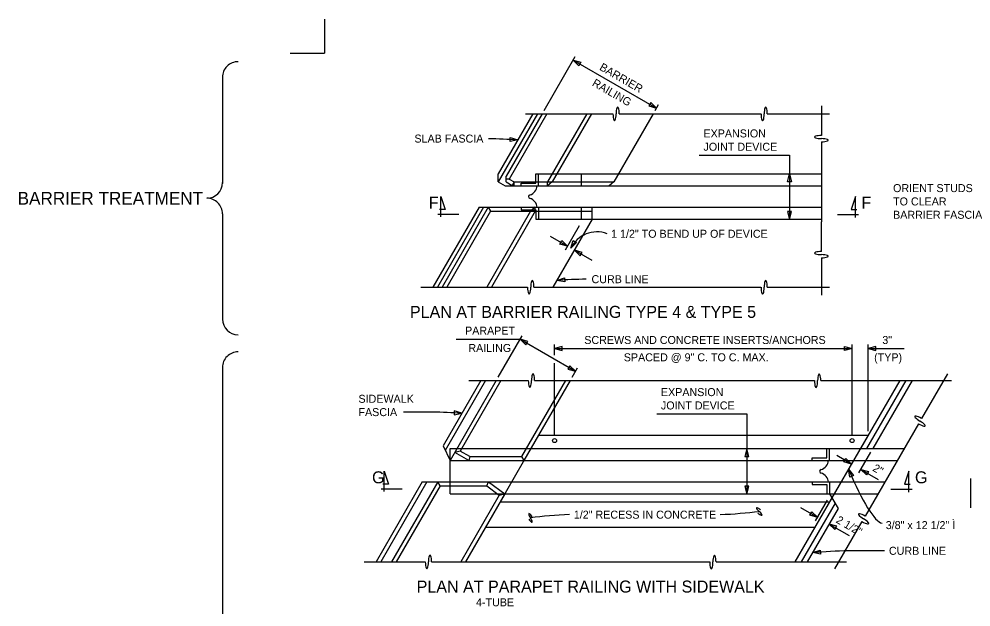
# Model space of a CAD drawing. Extents: x 19590 to 20151, y 19944 to 20103.
# Drawn here: x 19793.8 to 19849.3, y 20063.8 to 20098.1 of the extents above; entities that cross this region are included whole.
import ezdxf

# ---------------------------------------------------------------- set-up
doc = ezdxf.new("R2010")
doc.units = 0
for name, color, linetype in [('DETAIL_PR', 7, 'Continuous'), ('DETAIL_TEXT_DIMEN_PR', 7, 'Continuous'), ('Level 1', 7, 'Continuous'), ('MT_PAVT_MRKGS_EX', 7, 'Continuous'), ('MT_PAVT_MRKGS_EX_REF', 7, 'Continuous'), ('PAVT_MRKGS_QUANT', 7, 'Continuous')]:
    doc.layers.add(name, color=color, linetype=linetype)

# ---------------------------------------------------------------- blocks, each defined once
blk = doc.blocks.new('EJ3H')
at = {"layer": 'MT_PAVT_MRKGS_EX_REF'}
blk.add_text('4-TUBE', height=0.4665, dxfattribs=at).set_placement((8.843, -32.253))

msp = doc.modelspace()

# ---------------------------------------------------------------- linework, layer by layer
at = {"layer": 'DETAIL_PR'}
for p, q in [((19811.624, 20098.097), (19811.624, 20096.106)), ((19809.634, 20096.106), (19811.624, 20096.106)), ((19840.607, 20093.028), (19840.607, 20091.306)), ((19824.053, 20092.561), (19821.763, 20088.596)), ((19823.783, 20092.561), (19821.763, 20089.063)), ((19824.322, 20092.561), (19822.23, 20088.937)), ((19824.591, 20092.561), (19822.4, 20088.767)), ((19823.353, 20092.561), (19828.449, 20092.561)), ((19826.926, 20092.561), (19824.636, 20088.596)), ((19827.195, 20092.561), (19824.905, 20088.596)), ((19830.786, 20092.561), (19828.497, 20088.596)), ((19828.816, 20092.561), (19837.08, 20092.561)), ((19837.447, 20092.561), (19841.074, 20092.561)), ((19840.607, 20090.939), (19840.607, 20086.263)), ((19821.763, 20088.596), (19821.763, 20089.062)), ((19822.23, 20088.596), (19822.23, 20088.937)), ((19822.4, 20088.767), (19822.23, 20088.767)), ((19822.4, 20088.767), (19822.696, 20088.596)), ((19823.948, 20088.518), (19823.948, 20089.063)), ((19823.948, 20089.063), (19828.766, 20089.063)), ((19824.104, 20088.363), (19824.104, 20089.063)), ((19826.611, 20088.363), (19826.611, 20089.063)), ((19828.766, 20089.062), (19840.607, 20089.062)), ((19821.763, 20088.596), (19822.167, 20088.363)), ((19822.167, 20088.363), (19823.093, 20088.363)), ((19822.23, 20088.596), (19822.58, 20088.394)), ((19822.696, 20088.596), (19822.58, 20088.394)), ((19822.58, 20088.394), (19822.696, 20088.363)), ((19822.696, 20088.596), (19828.497, 20088.596)), ((19822.696, 20088.363), (19822.696, 20088.596)), ((19823.093, 20088.363), (19823.093, 20088.518)), ((19823.093, 20088.518), (19823.948, 20088.518)), ((19823.093, 20088.363), (19840.607, 20088.363)), ((19824.636, 20088.363), (19824.636, 20088.596)), ((19824.905, 20088.596), (19824.636, 20088.363)), ((19828.497, 20088.596), (19828.227, 20088.363)), ((19820.641, 20087.119), (19817.947, 20082.454)), ((19820.91, 20087.119), (19818.217, 20082.454)), ((19821.18, 20087.119), (19818.486, 20082.454)), ((19820.641, 20087.119), (19823.968, 20087.119)), ((19821.18, 20087.119), (19821.314, 20086.885)), ((19823.093, 20087.119), (19823.093, 20086.963)), ((19823.093, 20087.119), (19840.607, 20087.119)), ((19823.918, 20087.119), (19823.649, 20086.885)), ((19823.918, 20086.885), (19823.918, 20087.119)), ((19824.104, 20087.119), (19824.104, 20086.419)), ((19826.611, 20086.419), (19826.611, 20087.119)), ((19827.24, 20086.419), (19827.24, 20087.119)), ((19821.314, 20086.886), (19818.755, 20082.454)), ((19823.649, 20086.885), (19821.09, 20082.454)), ((19821.314, 20086.885), (19827.24, 20086.885)), ((19823.918, 20086.885), (19821.359, 20082.454)), ((19823.093, 20086.963), (19823.948, 20086.963)), ((19823.948, 20086.963), (19823.948, 20086.419)), ((19823.948, 20086.419), (19827.24, 20086.419)), ((19827.24, 20086.419), (19824.95, 20082.454)), ((19827.24, 20086.419), (19840.607, 20086.419)), ((19840.607, 20084.542), (19840.607, 20086.263)), ((19840.607, 20084.175), (19840.607, 20081.987)), ((19817.248, 20082.454), (19823.473, 20082.454)), ((19823.84, 20082.454), (19837.08, 20082.454)), ((19837.447, 20082.454), (19841.074, 20082.454))]:
    msp.add_line(p, q, dxfattribs=at)
for centre, radius, start, end in [((19823.421, 20088.428), 0.618, 288.1365, 353.9316), ((19823.621, 20087.741), 0.101, 94.4387, 265.5613), ((19823.421, 20087.053), 0.618, 6.0684, 71.8635)]:
    msp.add_arc(centre, radius, start, end, dxfattribs=at)
for centre, major_axis, ratio, start_param, end_param in [((19828.725, 20092.561), (0, -0.398), 0.230204, 1.570796, 4.712389), ((19837.355, 20092.561), (0, -0.398), 0.230204, 1.570796, 4.712389), ((19828.541, 20092.561), (0, -0.398), 0.230206, 4.712389, 7.853982), ((19837.172, 20092.561), (0, -0.398), 0.230206, 4.712389, 7.853982), ((19840.607, 20091.215), (0.398, 0), 0.230204, 1.570796, 4.712389), ((19840.607, 20091.031), (0.398, 0), 0.230206, 4.712389, 7.853982), ((19840.607, 20084.45), (0.398, 0), 0.230204, 1.570796, 4.712389), ((19840.607, 20084.267), (0.398, 0), 0.230206, 4.712389, 7.853982), ((19823.748, 20082.454), (0, -0.398), 0.230204, 1.570796, 4.712389), ((19837.355, 20082.454), (0, -0.398), 0.230204, 1.570796, 4.712389), ((19823.565, 20082.454), (0, -0.398), 0.230206, 4.712389, 7.853982), ((19837.172, 20082.454), (0, -0.398), 0.230206, 4.712389, 7.853982)]:
    msp.add_ellipse(centre, major_axis=major_axis, ratio=ratio, start_param=start_param, end_param=end_param, dxfattribs=at)
at = {"layer": 'DETAIL_TEXT_DIMEN_PR'}
for p, q in [((19824.439, 20092.764), (19826.252, 20095.904)), ((19826.135, 20095.702), (19830.983, 20092.903)), ((19805.683, 20094.698), (19805.683, 20088.513)), ((19830.903, 20092.764), (19831.1, 20093.105)), ((19833.484, 20090.151), (19838.741, 20090.151)), ((19838.741, 20090.151), (19838.741, 20086.419)), ((19818.412, 20086.56), (19818.411, 20087.741)), ((19818.411, 20087.741), (19818.666, 20086.998)), ((19842.59, 20087.741), (19842.334, 20086.998)), ((19842.589, 20086.532), (19842.59, 20087.741)), ((19805.683, 20086.737), (19805.683, 20080.595)), ((19819.461, 20086.691), (19818.244, 20086.691)), ((19818.666, 20086.998), (19818.333, 20086.998)), ((19841.54, 20086.691), (19842.766, 20086.691)), ((19842.334, 20086.998), (19842.668, 20086.998)), ((19825.678, 20084.647), (19826.495, 20086.061)), ((19824.785, 20085.433), (19825.795, 20084.85)), ((19826.199, 20084.617), (19827.209, 20084.033)), ((19805.683, 20077.779), (19805.683, 20063.131))]:
    msp.add_line(p, q, dxfattribs=at)
for centre, radius, start, end in [((19806.593, 20094.699), 0.91, 89.9663, 180.0337), ((19820.46, 20051.63), 39.492, 86.4465, 88.9222), ((19804.773, 20088.558), 0.911, 269.9663, 359.9663), ((19804.773, 20086.737), 0.91, 359.9663, 90.0337), ((19827.511, 20084.007), 1.679, 69.1378, 154.3845), ((19827.631, 20043.442), 39.492, 91.0778, 93.5535), ((19806.593, 20080.596), 0.91, 180.0337, 270.0337), ((19806.593, 20077.78), 0.91, 89.9663, 180.0337)]:
    msp.add_arc(centre, radius, start, end, dxfattribs=at)
at = {"layer": 'Level 1'}
for p, q in [((19826.135, 20095.702), (19826.584, 20095.577)), ((19826.468, 20095.375), (19826.135, 20095.702)), ((19826.584, 20095.577), (19826.468, 20095.375)), ((19830.65, 20093.23), (19830.534, 20093.028)), ((19830.983, 20092.903), (19830.65, 20093.23)), ((19830.534, 20093.028), (19830.983, 20092.903)), ((19822.45, 20090.954), (19822.463, 20091.187)), ((19822.908, 20091.045), (19822.45, 20090.954)), ((19822.463, 20091.187), (19822.908, 20091.045)), ((19838.624, 20088.611), (19838.741, 20089.062)), ((19838.741, 20089.062), (19838.858, 20088.611)), ((19838.858, 20088.611), (19838.624, 20088.611)), ((19838.857, 20086.871), (19838.624, 20086.871)), ((19838.624, 20086.871), (19838.741, 20086.419)), ((19838.741, 20086.419), (19838.857, 20086.871)), ((19825.345, 20084.975), (19825.462, 20085.177)), ((19825.795, 20084.849), (19825.345, 20084.975)), ((19825.462, 20085.177), (19825.795, 20084.849)), ((19825.997, 20084.733), (19826.122, 20085.183)), ((19826.324, 20085.066), (19825.997, 20084.733)), ((19826.122, 20085.183), (19826.324, 20085.066)), ((19826.199, 20084.617), (19826.532, 20084.29)), ((19826.648, 20084.492), (19826.199, 20084.617)), ((19826.532, 20084.29), (19826.648, 20084.492)), ((19825.184, 20082.857), (19825.629, 20082.999)), ((19825.641, 20082.766), (19825.184, 20082.857)), ((19825.629, 20082.999), (19825.641, 20082.766))]:
    msp.add_line(p, q, dxfattribs=at)
at = {"layer": 'MT_PAVT_MRKGS_EX'}
for p, q in [((19847.944, 20077.416), (19846.441, 20074.812)), ((19820.746, 20077.011), (19818.546, 20073.201)), ((19821.015, 20077.011), (19818.667, 20072.944)), ((19821.644, 20077.011), (19818.95, 20072.346)), ((19821.913, 20077.011), (19819.542, 20072.904)), ((19820.046, 20077.011), (19823.515, 20077.011)), ((19825.684, 20077.011), (19823.125, 20072.579)), ((19825.953, 20077.011), (19823.26, 20072.346)), ((19823.881, 20077.011), (19840.198, 20077.011)), ((19840.565, 20077.011), (19848.177, 20077.011)), ((19845.166, 20077.011), (19842.877, 20073.046)), ((19845.526, 20077.011), (19843.236, 20073.046)), ((19845.885, 20077.011), (19843.595, 20073.046)), ((19846.257, 20074.494), (19843.15, 20069.113)), ((19824.113, 20073.823), (19821.868, 20069.936)), ((19824.113, 20073.823), (19843.326, 20073.823)), ((19843.326, 20073.823), (19841.081, 20069.936)), ((19818.546, 20073.201), (19818.95, 20072.346)), ((19818.95, 20073.046), (19823.664, 20073.046)), ((19818.95, 20072.346), (19818.95, 20073.046)), ((19818.95, 20073.046), (19842.877, 20073.046)), ((19819.542, 20072.904), (19819.222, 20072.817)), ((19820.049, 20072.346), (19819.222, 20072.817)), ((19820.112, 20072.579), (19819.542, 20072.904)), ((19840.926, 20072.502), (19840.926, 20073.046)), ((19841.081, 20072.346), (19841.081, 20073.046)), ((19842.877, 20073.046), (19845.421, 20073.046)), ((19818.95, 20071.102), (19818.95, 20072.346)), ((19818.95, 20072.346), (19823.26, 20072.346)), ((19820.112, 20072.579), (19820.049, 20072.346)), ((19820.112, 20072.579), (19823.125, 20072.579)), ((19823.125, 20072.579), (19823.26, 20072.346)), ((19823.26, 20072.346), (19842.473, 20072.346)), ((19840.07, 20072.346), (19840.07, 20072.502)), ((19840.07, 20072.502), (19840.926, 20072.502)), ((19842.473, 20072.346), (19845.017, 20072.346)), ((19817.334, 20071.102), (19814.64, 20066.437)), ((19817.603, 20071.102), (19814.91, 20066.437)), ((19818.231, 20071.102), (19815.538, 20066.437)), ((19817.334, 20071.102), (19818.95, 20071.102)), ((19818.367, 20070.869), (19818.231, 20071.102)), ((19818.95, 20070.402), (19818.95, 20071.102)), ((19818.95, 20071.102), (19822.542, 20071.102)), ((19821.096, 20070.869), (19821.192, 20071.102)), ((19821.192, 20071.102), (19822.137, 20070.402)), ((19822.542, 20071.102), (19841.755, 20071.102)), ((19840.07, 20071.102), (19840.07, 20070.947)), ((19840.07, 20070.947), (19840.926, 20070.947)), ((19840.926, 20070.947), (19840.926, 20070.402)), ((19841.081, 20071.102), (19841.081, 20070.402)), ((19841.755, 20071.102), (19844.299, 20071.102)), ((19849.321, 20069.603), (19849.321, 20071.313)), ((19818.367, 20070.869), (19815.807, 20066.437)), ((19818.367, 20070.869), (19821.096, 20070.869)), ((19818.95, 20070.402), (19822.137, 20070.402)), ((19818.95, 20070.402), (19841.351, 20070.402)), ((19822.137, 20070.402), (19819.848, 20066.437)), ((19821.096, 20070.869), (19821.825, 20070.329)), ((19821.825, 20070.329), (19822.137, 20070.402)), ((19841.081, 20070.402), (19841.575, 20069.547)), ((19841.351, 20070.402), (19843.895, 20070.402)), ((19821.825, 20070.329), (19819.578, 20066.437)), ((19821.868, 20069.936), (19841.081, 20069.936)), ((19841.216, 20070.169), (19839.061, 20066.437)), ((19841.396, 20069.858), (19839.42, 20066.437)), ((19841.575, 20069.547), (19839.78, 20066.437)), ((19842.967, 20068.795), (19841.372, 20066.033)), ((19821.015, 20068.458), (19840.228, 20068.458)), ((19813.94, 20066.437), (19817.509, 20066.437)), ((19817.876, 20066.437), (19834.093, 20066.437)), ((19834.46, 20066.437), (19842.072, 20066.437))]:
    msp.add_line(p, q, dxfattribs=at)
for centre in [(19825.046, 20073.512), (19842.393, 20073.512)]:
    msp.add_circle(centre, 0.117, dxfattribs=at)
for centre, radius, start, end in [((19840.399, 20072.412), 0.618, 288.1365, 353.9316), ((19840.599, 20071.724), 0.101, 94.4387, 265.5613), ((19840.399, 20071.037), 0.618, 6.0684, 71.8635)]:
    msp.add_arc(centre, radius, start, end, dxfattribs=at)
for centre, major_axis, ratio, start_param, end_param in [((19823.79, 20077.011), (0, -0.398), 0.230204, 1.570796, 4.712389), ((19840.473, 20077.011), (0, -0.398), 0.230204, 1.570796, 4.712389), ((19823.606, 20077.011), (0, -0.398), 0.230206, 4.712389, 7.853982), ((19840.29, 20077.011), (0, -0.398), 0.230206, 4.712389, 7.853982), ((19846.395, 20074.733), (0.345, -0.199), 0.230204, 1.570796, 4.712389), ((19846.303, 20074.574), (0.345, -0.199), 0.230206, 4.712389, 7.853982), ((19823.692, 20069.043), (0.148, -0.221), 0.230204, 1.570796, 4.712389), ((19837.015, 20069.432), (0.205, -0.169), 0.230204, 1.570796, 4.712389), ((19836.937, 20069.338), (0.205, -0.169), 0.230206, 4.712389, 7.853982), ((19843.104, 20069.033), (0.345, -0.199), 0.230204, 1.570796, 4.712389), ((19823.59, 20068.975), (0.148, -0.221), 0.230206, 4.712389, 7.853982), ((19843.013, 20068.874), (0.345, -0.199), 0.230206, 4.712389, 7.853982), ((19817.784, 20066.437), (0, -0.398), 0.230204, 1.570796, 4.712389), ((19834.368, 20066.437), (0, -0.398), 0.230204, 1.570796, 4.712389), ((19817.601, 20066.437), (0, -0.398), 0.230206, 4.712389, 7.853982), ((19834.185, 20066.437), (0, -0.398), 0.230206, 4.712389, 7.853982)]:
    msp.add_ellipse(centre, major_axis=major_axis, ratio=ratio, start_param=start_param, end_param=end_param, dxfattribs=at)
at = {"layer": 'MT_PAVT_MRKGS_EX_REF'}
for p, q in [((19819.303, 20079.421), (19823.035, 20079.421)), ((19821.76, 20077.213), (19823.152, 20079.623)), ((19823.035, 20079.421), (19826.267, 20077.555)), ((19825.046, 20078.493), (19825.046, 20079.111)), ((19825.046, 20078.877), (19842.393, 20078.877)), ((19842.393, 20073.823), (19842.393, 20079.111)), ((19843.326, 20074.057), (19843.326, 20079.111)), ((19843.326, 20078.877), (19845.425, 20078.877)), ((19825.046, 20073.823), (19825.046, 20078.027)), ((19826.07, 20077.213), (19826.384, 20077.757)), ((19831.004, 20075.068), (19836.261, 20075.068)), ((19836.26, 20075.068), (19836.26, 20070.402)), ((19842.359, 20072.149), (19841.501, 20072.645)), ((19842.781, 20071.636), (19843.479, 20072.844)), ((19815.105, 20070.543), (19815.104, 20071.724)), ((19815.104, 20071.724), (19815.359, 20070.982)), ((19842.898, 20071.838), (19843.908, 20071.255)), ((19845.707, 20071.724), (19845.452, 20070.982)), ((19845.707, 20070.516), (19845.707, 20071.724)), ((19815.359, 20070.982), (19815.026, 20070.982)), ((19845.452, 20070.982), (19845.786, 20070.982)), ((19816.154, 20070.674), (19814.937, 20070.674)), ((19844.658, 20070.674), (19845.884, 20070.674)), ((19840.267, 20068.837), (19840.964, 20070.045)), ((19839.374, 20069.622), (19840.384, 20069.039)), ((19841.057, 20068.65), (19842.225, 20067.976))]:
    msp.add_line(p, q, dxfattribs=at)
for centre, start, end in [((19817.198, 20035.691), 86.4465, 91.4029), ((19843.103, 20027.605), 88.2954, 94.3693)]:
    msp.add_arc(centre, 39.492, start, end, dxfattribs=at)
at = {"layer": 'PAVT_MRKGS_QUANT'}
for p, q in [((19823.035, 20079.421), (19823.368, 20079.094)), ((19823.485, 20079.296), (19823.035, 20079.421)), ((19823.368, 20079.094), (19823.485, 20079.296)), ((19825.498, 20078.994), (19825.046, 20078.877)), ((19825.046, 20078.877), (19825.498, 20078.761)), ((19825.498, 20078.761), (19825.498, 20078.994)), ((19841.941, 20078.761), (19841.941, 20078.994)), ((19841.941, 20078.994), (19842.393, 20078.877)), ((19842.393, 20078.877), (19841.941, 20078.761)), ((19843.778, 20078.994), (19843.326, 20078.877)), ((19843.326, 20078.877), (19843.778, 20078.761)), ((19843.778, 20078.761), (19843.778, 20078.994)), ((19825.934, 20077.882), (19825.818, 20077.68)), ((19825.818, 20077.68), (19826.267, 20077.555)), ((19826.267, 20077.555), (19825.934, 20077.882)), ((19819.201, 20075.248), (19819.188, 20075.015)), ((19819.188, 20075.015), (19819.646, 20075.106)), ((19819.646, 20075.106), (19819.201, 20075.248)), ((19836.26, 20073.046), (19836.144, 20072.594)), ((19836.377, 20072.594), (19836.26, 20073.046)), ((19836.144, 20072.594), (19836.377, 20072.594)), ((19841.91, 20072.274), (19842.026, 20072.476)), ((19842.359, 20072.149), (19841.91, 20072.274)), ((19842.026, 20072.476), (19842.359, 20072.149)), ((19842.185, 20071.848), (19842.471, 20071.479)), ((19842.257, 20071.387), (19842.185, 20071.848)), ((19843.231, 20071.511), (19842.898, 20071.838)), ((19842.898, 20071.838), (19843.348, 20071.713)), ((19843.348, 20071.713), (19843.231, 20071.511)), ((19842.471, 20071.479), (19842.257, 20071.387)), ((19836.377, 20070.854), (19836.143, 20070.854)), ((19836.143, 20070.854), (19836.26, 20070.402)), ((19836.26, 20070.402), (19836.377, 20070.854)), ((19839.934, 20069.164), (19840.051, 20069.366)), ((19840.051, 20069.366), (19840.384, 20069.039)), ((19840.384, 20069.039), (19839.934, 20069.164)), ((19841.507, 20068.525), (19841.057, 20068.65)), ((19841.057, 20068.65), (19841.39, 20068.323)), ((19841.39, 20068.323), (19841.507, 20068.525)), ((19840.094, 20066.982), (19840.539, 20067.123)), ((19840.539, 20067.123), (19840.552, 20066.89)), ((19840.552, 20066.89), (19840.094, 20066.982))]:
    msp.add_line(p, q, dxfattribs=at)
for centre, major_axis, start_param, end_param in [((19842.219, 20075.017), (2.026, -6.314), 5.183087, 6.19004), ((19834.048, 20070.297), (6.628, 0.225), 4.805942, 5.164147), ((19826.568, 20068.104), (-6.628, -0.225), 4.805942, 5.164147)]:
    msp.add_ellipse(centre, major_axis=major_axis, ratio=0.169331, start_param=start_param, end_param=end_param, dxfattribs=at)

# ---------------------------------------------------------------- block references
at = {"layer": 'Level 1'}
msp.add_blockref('EJ3H', (19811.624, 20096.106), dxfattribs=at)

# ---------------------------------------------------------------- texts
at = {"layer": 'DETAIL_TEXT_DIMEN_PR'}
for s, height, rotation, p in [('BARRIER', 0.4665, 330, (19827.62, 20095.159)), ('RAILING', 0.4665, 330, (19827.195, 20094.237)), ('BARRIER TREATMENT', 0.74643, 360, (19793.742, 20087.273))]:
    msp.add_text(s, height=height, rotation=rotation, dxfattribs=at).set_placement(p)
for s, height, p in [('EXPANSION ', 0.4665, (19833.727, 20091.193)), ('SLAB FASCIA', 0.46652, (19816.875, 20090.893)), ('JOINT DEVICE', 0.46652, (19833.727, 20090.416)), ('ORIENT STUDS ', 0.46652, (19844.781, 20088.005)), ('F', 0.7, (19817.712, 20087.041)), ('F', 0.7, (19842.939, 20087.041)), ('TO CLEAR', 0.4665, (19844.781, 20087.228)), ('BARRIER FASCIA', 0.46652, (19844.781, 20086.45)), ('1 1/2" TO BEND UP OF DEVICE', 0.46652, (19828.342, 20085.343)), ('CURB LINE', 0.4665, (19827.2, 20082.694)), ('PLAN AT BARRIER RAILING TYPE 4 & TYPE 5', 0.69987, (19816.613, 20080.671))]:
    msp.add_text(s, height=height, dxfattribs=at).set_placement(p)
at = {"layer": 'MT_PAVT_MRKGS_EX_REF'}
for s, height, p in [('PARAPET', 0.4665, (19819.827, 20079.693)), ('SCREWS AND CONCRETE INSERTS/ANCHORS', 0.46652, (19826.779, 20079.149)), ('3"', 0.4665, (19844.153, 20079.149)), ('RAILING', 0.4665, (19820.02, 20078.682)), ('SPACED @ 9" C. TO C. MAX.', 0.46652, (19829.081, 20078.139)), ('(TYP)', 0.4665, (19843.677, 20078.139)), ('EXPANSION ', 0.4665, (19831.247, 20076.11)), ('SIDEWALK', 0.4665, (19813.614, 20075.72)), ('FASCIA', 0.4665, (19813.614, 20074.943)), ('JOINT DEVICE', 0.46652, (19831.247, 20075.332)), ('G', 0.7, (19814.405, 20071.024)), ('G', 0.7, (19846.057, 20071.025)), ('1/2" RECESS IN CONCRETE', 0.46652, (19826.168, 20068.964)), ('3/8" x 12 1/2" Ì', 0.46652, (19844.352, 20068.354)), ('CURB LINE', 0.4665, (19844.538, 20066.857)), ('PLAN AT PARAPET RAILING WITH SIDEWALK', 0.69987, (19817.006, 20064.654))]:
    msp.add_text(s, height=height, dxfattribs=at).set_placement(p)
for s, p in [('2"', (19843.545, 20071.779)), ('2 1/2"', (19841.411, 20068.757))]:
    msp.add_text(s, height=0.4665, rotation=330, dxfattribs=at).set_placement(p)

doc.saveas('drawing.dxf')
